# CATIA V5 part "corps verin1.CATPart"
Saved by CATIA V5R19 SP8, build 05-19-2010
Part number: corps verin1
Bounding box of the stored display mesh (mm): x -3.5 to 27.224, y -4.5 to 4.5, z -3.329 to 27.224
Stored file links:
  G:\EU_thinkMotion\CFAO_2010\MMS_groupe1\MMS_groupe1\A reprendre\OK\glenerrant\glenerrant\glenerrant\corps verin1.CATPart
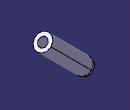
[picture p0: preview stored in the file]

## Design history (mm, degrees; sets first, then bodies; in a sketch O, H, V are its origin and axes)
Set1
  Point1: (45, 0, 45)
  Point2: (0, 0, 0)
  Line1: type PtPt, FirstPoint Point2, SecondPoint Point1
  Plane1: type Normal, Curve Line1, RefPoint Point2
Body1 (main body)
  Sketch1 on zx-plane, origin (0, 0, 0), H (-1, 0, 0), V (0, 0, 1)
    circle A1 centre (0, 0) radius 2
    point P1 (0, 0)
    circle A2 centre (0, 0) radius 3.5
    point P2 (0, 0)
    reference projected point E1 (0, 0) from Point2
    reference projected point E2 (0, 0) from Point2
    radius A2 = 3.5
    radius A1 = 2
    coincidence: P2 E1, P1 E2
  Pad1: profile Sketch1, direction (0, 1, 0), length 1, opposite side length 1
  Sketch2 on Plane1, origin (0, 0, 0), H (0, 1, 0), V (-0.7071, 0, 0.7071)
    circle A1 centre (0, 0) radius 4.5
    point P1 (0, 0)
    reference projected point E1 (0, 0) from Line1
    radius A1 = 4.5
    coincidence: E1 P1
  Pad2: profile Sketch2, direction (0.7071, 0, 0.7071), length 34, opposite side length -2.5
  Sketch3 on end face of Pad2, origin (24.0416, 0, 24.0416), H (0.7071, 0, -0.7071), V (0, 1, 0)
    point P1 (0, 0)
    construction circle A1 centre (0, 0) radius 2.5
    radius A1 = 2.5
  Hole1: placed by Sketch3, at (24.0416, 0, 24.0416) direction (-0.7071, 0, -0.7071), diameter 5, depth 30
